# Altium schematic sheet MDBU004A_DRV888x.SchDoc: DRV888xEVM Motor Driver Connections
size 431 x 279 mm; Date: Not shown in title block; ApprovedBy: Not shown in title block; CheckedBy: Not shown in title block; Author: Not shown in title block; CompanyName: Not shown in title block; Engineer: Not shown in title block; Organization: Not shown in title block; Address1: Not shown in title block; Address2: Not shown in title block; Address3: Not shown in title block; Address4: Not shown in title block; DocumentNumber: 1; Revision: Use project parameter SCH_Rev; SheetNumber: 1; SheetTotal: 3; PageSetup: Record=PageOptions¦CenterHorizontal=True¦CenterVertical=True¦PrintScale=1.00¦XCorrection=1.00¦YCorrection=1.00¦PrintKind=0¦BorderSize=5000000¦LeftOffset=0¦BottomOffset=0¦Orientation=2¦PaperLength=1000¦PaperWidth=1000¦Scale=100¦PaperSource=15¦PrintQuality=600¦MediaType=1¦DitherType=10¦PaperKind=Letter¦PrintScaleMode=1
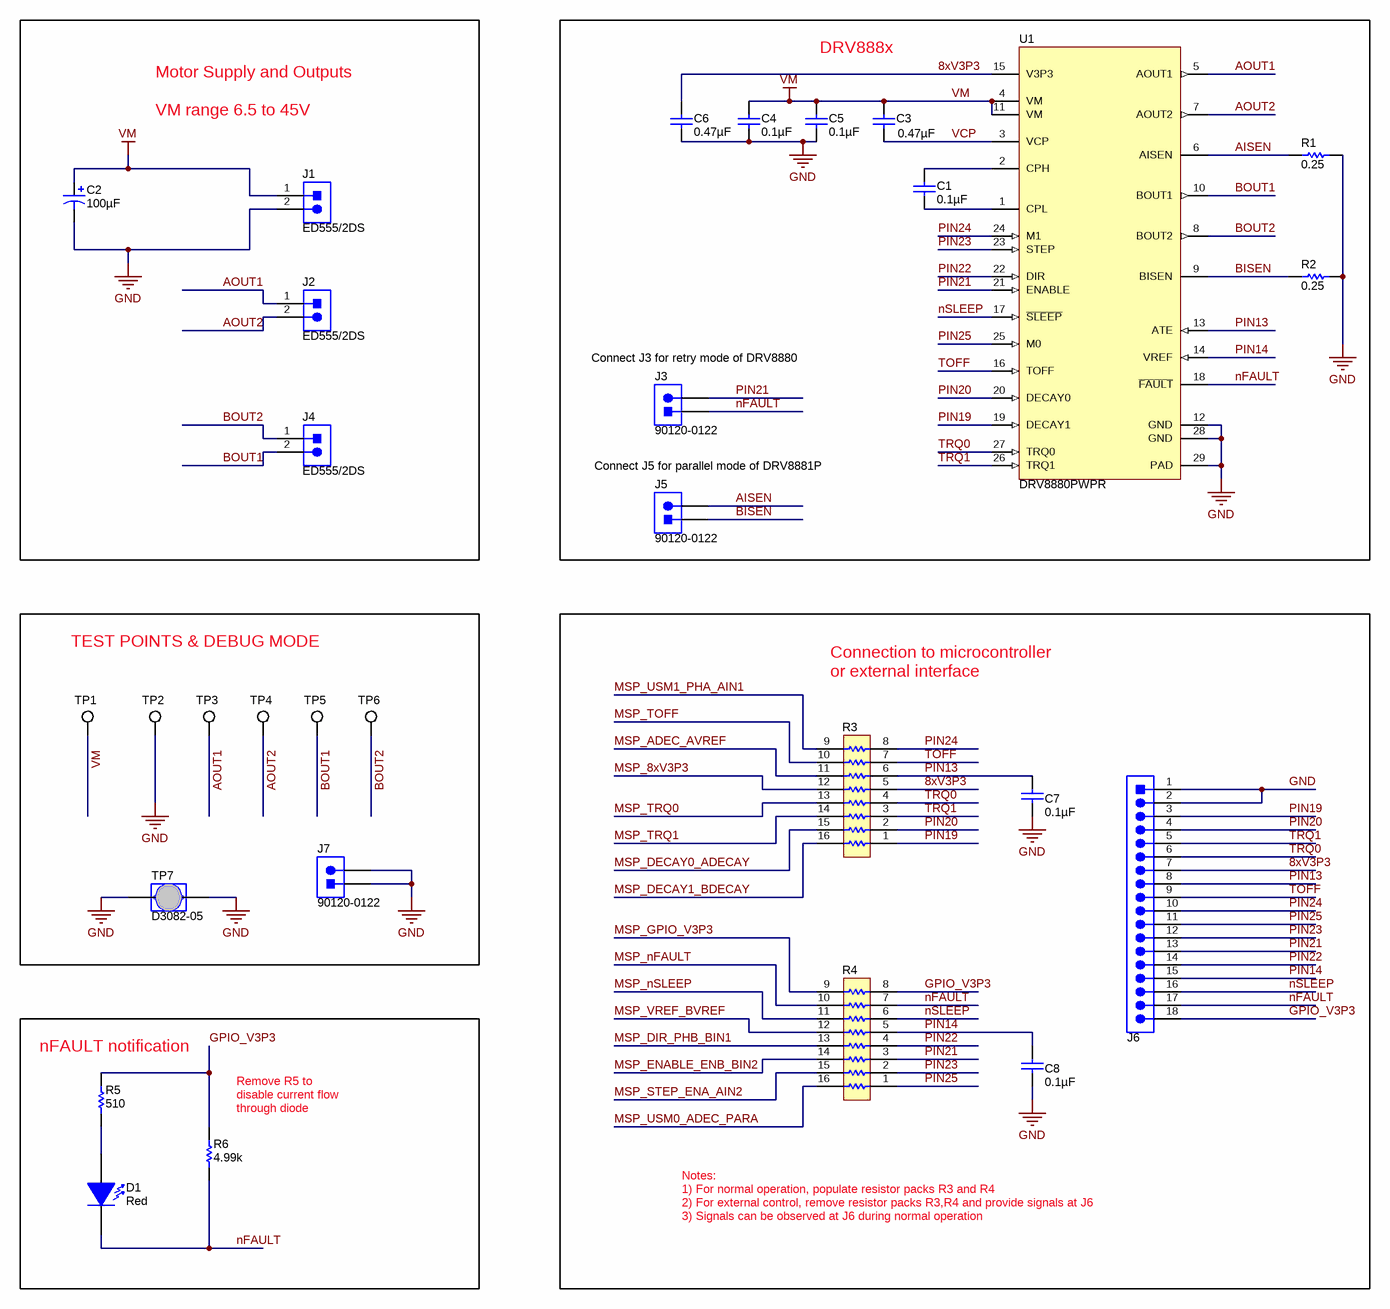
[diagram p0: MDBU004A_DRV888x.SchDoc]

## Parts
C1  ValueDisplayed: 0.1µF  [0805L]  (hidden comment: C0805C104K1RACTU)
C2  ValueDisplayed: 100µF  [SM_RADIAL_G]  (hidden comment: EEE-FK1J101P)
C3  ValueDisplayed: 0.47µF  [0805L]  (hidden comment: C2012X7R1E474K)
C4  ValueDisplayed: 0.1µF  [0805L]  (hidden comment: C0805C104K1RACTU)
C5  ValueDisplayed: 0.1µF  [0805L]  (hidden comment: C0805C104K1RACTU)
C6  ValueDisplayed: 0.47µF  [0603L]  (hidden comment: C0603C474K9RACTU)
C7  ValueDisplayed: 0.1µF  [0402L]  (hidden comment: GRM155R61A104KA01D)
C8  ValueDisplayed: 0.1µF  [0402L]  (hidden comment: GRM155R61A104KA01D)
D1  value Red  [LED_LTST-C190_Red]  (hidden comment: LTST-C190CKT)
J1  ED555/2DS  [TERM_BLK_ED555-2DS]
J2  ED555/2DS  [TERM_BLK_ED555-2DS]
J3  90120-0122  [CONN_90120-0122]
J4  ED555/2DS  [TERM_BLK_ED555-2DS]
J5  90120-0122  [CONN_90120-0122]
J6  TSW-118-07-G-S  [TSW-118-07-G-S]  (value not drawn)
J7  90120-0122  [CONN_90120-0122]
R1  value 0.25  [2010L]  (hidden comment: CSRN2010FKR250)
R2  value 0.25  [2010L]  (hidden comment: CSRN2010FKR250)
R3  EXB-2HV330JV  [RESCAXS_EXB-2HV]  (value not drawn)
R4  EXB-2HV330JV  [RESCAXS_EXB-2HV]  (value not drawn)
R5  value 510  [0402L]  (hidden comment: CRCW0402510RJNED)
R6  value 4.99k  [0402L]  (hidden comment: CRCW04024K99FKED)
TP1  5016  [Testpoint_Keystone_Compact]  (value not drawn)
TP2  5016  [Testpoint_Keystone_Compact]  (value not drawn)
TP3  5016  [Testpoint_Keystone_Compact]  (value not drawn)
TP4  5016  [Testpoint_Keystone_Compact]  (value not drawn)
TP5  5016  [Testpoint_Keystone_Compact]  (value not drawn)
TP6  5016  [Testpoint_Keystone_Compact]  (value not drawn)
TP7  D3082-05  [Harwin_D3082-05]
U1  DRV8880PWPR  [PWP0028C_N]

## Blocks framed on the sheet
DRV888x: C1 C3-C6 J3 J5 R1 R2 U1
TEST POINTS & DEBUG MODE: J7 TP1-TP7
nFAULT notification: D1 R5 R6

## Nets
GND: C2.2(-) C4.1 C5.1 C6.2 C7.2 C8.2 J1.2 J6.1 J6.2 J7.1 J7.2 R1.1 R2.1 TP2.1 TP7.1 TP7.2 U1.12(GND) U1.28(GND) U1.29(PAD)
VM: C2.1(+) C3.2 C4.2 C5.2 J1.1 TP1.1 U1.4(VM) U1.11(VM)
8xV3P3: C6.1 J6.7 R3.5 U1.15(V3P3)
AISEN: J5.2 R1.2 U1.6(AISEN)
AOUT1: J2.1 TP3.1 U1.5(AOUT1)
AOUT2: J2.2 TP4.1 U1.7(AOUT2)
BISEN: J5.1 R2.2 U1.9(BISEN)
BOUT1: J4.2 TP5.1 U1.10(BOUT1)
BOUT2: J4.1 TP6.1 U1.8(BOUT2)
GPIO_V3P3: J6.18 R4.8 R5.2 R6.2
MSP_8xV3P3: R3.12
MSP_ADEC_AVREF: R3.11
MSP_DECAY0_ADECAY: R3.15
MSP_DECAY1_BDECAY: R3.16
MSP_DIR_PHB_BIN1: R4.13
MSP_ENABLE_ENB_BIN2: R4.14
MSP_GPIO_V3P3: R4.9
MSP_nFAULT: R4.10
MSP_nSLEEP: R4.11
MSP_STEP_ENA_AIN2: R4.15
MSP_TOFF: R3.10
MSP_TRQ0: R3.13
MSP_TRQ1: R3.14
MSP_USM0_ADEC_PARA: R4.16
MSP_USM1_PHA_AIN1: R3.9
MSP_VREF_BVREF: R4.12
nFAULT: D1.2(K) J3.1 J6.17 R4.7 R6.1 U1.18(~{FAULT})
nSLEEP: J6.16 R4.6 U1.17(~{SLEEP})
PIN13: C7.1 J6.8 R3.6 U1.13(ATE)
PIN14: C8.1 J6.15 R4.5 U1.14(VREF)
PIN19: J6.3 R3.1 U1.19(DECAY1)
PIN20: J6.4 R3.2 U1.20(DECAY0)
PIN21: J3.2 J6.13 R4.3 U1.21(ENABLE)
PIN22: J6.14 R4.4 U1.22(DIR)
PIN23: J6.12 R4.2 U1.23(STEP)
PIN24: J6.10 R3.8 U1.24(M1)
PIN25: J6.11 R4.1 U1.25(M0)
TOFF: J6.9 R3.7 U1.16(TOFF)
TRQ0: J6.6 R3.4 U1.27(TRQ0)
TRQ1: J6.5 R3.3 U1.26(TRQ1)
VCP: C3.1 U1.3(VCP)
NetC1_1: C1.1 U1.1(CPL)
NetC1_2: C1.2 U1.2(CPH)
NetD1_1: D1.1(A) R5.1

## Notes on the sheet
- Motor Supply and Outputs
  VM range 6.5 to 45V
- (near J3) Connect J3 for retry mode of DRV8880
- Connect J5 for parallel mode of DRV8881P
- Connection to microcontroller
  or external interface
- (near R6) Remove R5 to disable current flow through diode
- Notes:
  1) For normal operation, populate resistor packs R3 and R4
  2) For external control, remove resistor packs R3,R4 and provide signals at J6
  3) Signals can be observed at J6 during normal operation

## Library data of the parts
C1 C4 C5 = C0805C104K1RACTU: CAP, CERM, 0.1 µF, 100 V, +/- 10%, X7R, 0805; Manufacturer: Kemet; Polarized: N; CompType: Capacitor; Value: 0.1uF; U/M: EA; Cap_F: 0.0000001; Tolerance_%: 10; ESR_ohm: 0.064; Value1: 0.064 ohm; VDC_V: 100; Value2: 100V; IRMS_A: 1.64; TaMin_C: -55; TaMax_C: 125; Cap_Case: 0805
C2 = EEE-FK1J101P: CAP, AL, 100 µF, 63 V, +/- 20%, 0.35 ohm, SMD; Manufacturer: Panasonic; Value: 100uF; Polarized: Y; CompType: Capacitor; U/M: EA; Cap_F: 0.0001; Tolerance_%: 20; ESR_ohm: 0.35; VDC_V: 63; Value2: 63V; IRMS_A: 0.4; TaMin_C: -55; TaMax_C: 105; Cap_Case: G
C3 = C2012X7R1E474K: CAP, CERM, 0.47 µF, 25 V, +/- 10%, X7R, 0805; Manufacturer: TDK; Polarized: N; CompType: Capacitor; Value: 0.47uF; U/M: EA; Cap_F: 0.00000047; Tolerance_%: 10; ESR_ohm: 0.0101; Value1: 0.0101 ohm; VDC_V: 25; Value2: 25V; TaMin_C: -55; TaMax_C: 125; Cap_Case: 0805
C6 = C0603C474K9RACTU: CAP, CERM, 0.47 µF, 6.3 V, +/- 10%, X7R, 0603; Manufacturer: Kemet; Polarized: N; CompType: Capacitor; Value: 0.47uF; U/M: EA; Cap_F: 0.00000047; Tolerance_%: 10; Value1: Unknown; VDC_V: 6.3; Value2: 6.3V; TaMin_C: -55; TaMax_C: 125; Cap_Case: 0603
C7 C8 = GRM155R61A104KA01D: CAP, CERM, 0.1 µF, 10 V, +/- 10%, X5R, 0402; Manufacturer: MuRata; Value: 0.1uF; Polarized: N; CompType: Capacitor; U/M: EA; Cap_F: 0.0000001; Tolerance_%: 10; Value1: Unknown; Value2: 10V; TaMin_C: -55; TaMax_C: 85; Cap_Case: 0402
D1 = LTST-C190CKT: LED, Red, SMD; Manufacturer: Lite-On; Vf_V: 2; Value2: 2V; Io_A: 0.02; Tjmax_C: 85; Power_TotalModule: 0.0625; Value1: 0.0625W; U/M: EA
J1 J2 J4 = ED555/2DS: Terminal Block, 6A, 3.5mm Pitch, 2-Pos, TH; Manufacturer: On-Shore Technology; SymbolCreator: a0412235; CompType: Connector; U/M: EA
J3 J5 J7 = 90120-0122: Header, 100mil, 2x1, Tin, TH; Manufacturer: Molex; SymbolCreator: a0412235; U/M: EA
J6 = TSW-118-07-G-S: Header, 100mil, 18x1, Gold, TH; Manufacturer: Samtec; SymbolCreator: a0411947; U/M: EA
R1 R2 = CSRN2010FKR250: RES, 0.25, 1%, 1 W, 2010; Manufacturer: Stackpole Electronics Inc; CompType: Resistor; Value_Code: R250; Tolerance_%: 1; Value2: 1W; TempCo: 250 ppm/C; U/M: EA
R3 R4 = EXB-2HV330JV: RES, 33, 5%, 0.0625 W, Resistor Array - 8x1; Manufacturer: Panasonic; SymbolCreator: a0411947; Res_ohm: 33; Value: 33; Value_Code: 33R0; Tolerance_%: 5; Power_W: 0.0625; TempCo: 200 ppm/C; EIA_Code: E24; U/M: EA
R5 = CRCW0402510RJNED: RES, 510, 5%, 0.063 W, 0402; Manufacturer: Vishay-Dale; CompType: Resistor; Value_Code: 510R; Tolerance_%: 5; Power_W: 0.063; Value2: 0.063W; VDC_V: 50; TempCo: 200 ppm/C; EIA_Code: E24; U/M: EA
R6 = CRCW04024K99FKED: RES, 4.99 k, 1%, 0.063 W, 0402; Manufacturer: Vishay-Dale; CompType: Resistor; Res_ohm: 4990; Value_Code: 4k99; Tolerance_%: 1; Power_W: 0.063; Value2: 0.063W; VDC_V: 50; TempCo: 100 ppm/C; EIA_Code: E96; U/M: EA
TP1-TP6 = 5016: Test Point, Compact, SMT; Manufacturer: Keystone; CompType: Test Point Loop; U/M: EA
TP7 = D3082-05: 1mm Uninsulated Shorting Plug, 10.16mm spacing, TH; Manufacturer: Harwin; SymbolCreator: a0799628; CompType: Jumper Wire; U/M: EA
U1 = DRV8880PWPR: 2-A 45-V 1/16-μstep Stepper Motor Driver With AutoTune, PWP0028C; Manufacturer: Texas Instruments; SymbolCreator: Altium; CompType: IC; U/M: EA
